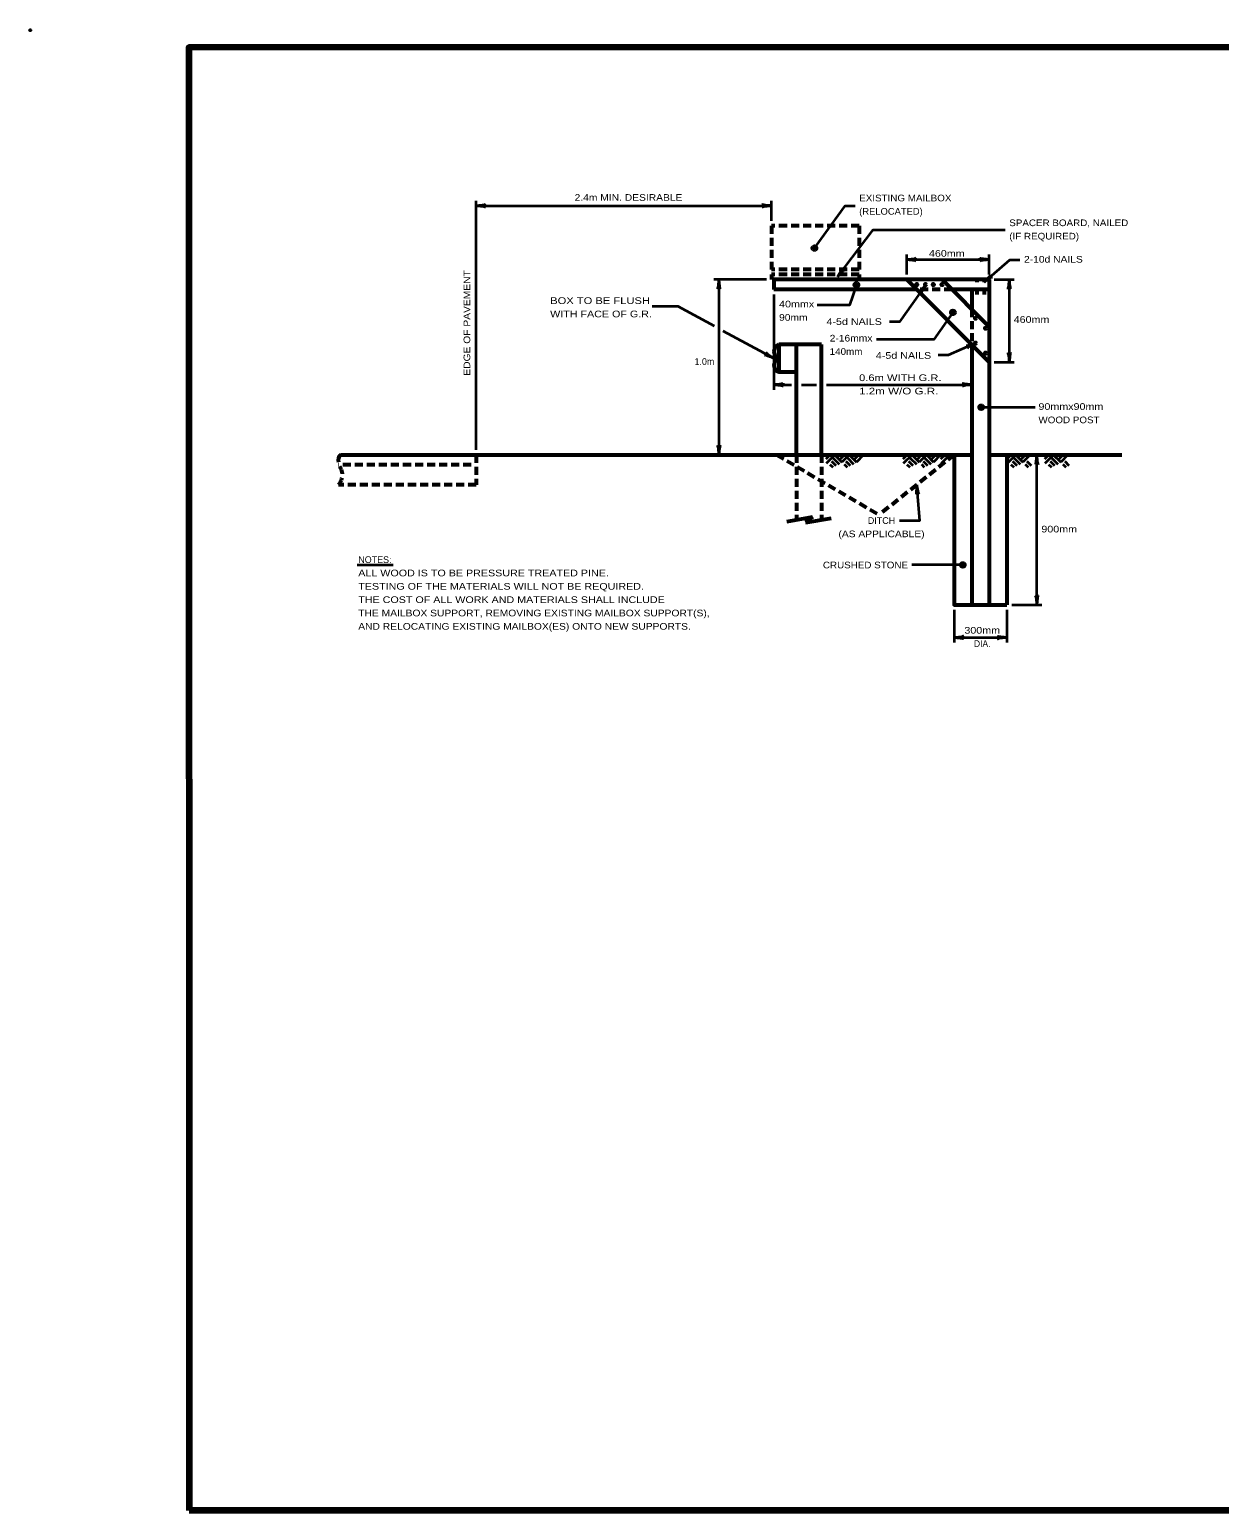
# Model space of a CAD drawing. Extents: x -123 to 733, y -435 to 109.
# Drawn here: x -123 to 305, y -424 to 109 of the extents above; entities that cross this region are included whole.
import ezdxf
from ezdxf.enums import TextEntityAlignment as Align

# ---------------------------------------------------------------- set-up
doc = ezdxf.new("R2010")
doc.units = 0
doc.header["$LTSCALE"] = 0.96
doc.header["$PDMODE"] = 32
doc.header["$PDSIZE"] = 0.48
doc.linetypes.add('MEDIUM_DASHED', pattern=[4.5, 3, -1.5])
doc.layers.add('1', color=7, linetype='Continuous', lineweight=35)

msp = doc.modelspace()

# ---------------------------------------------------------------- hatches: boundary and pattern name
at = {"layer": '1'}
for points in [[(160.1971, 29.9618, 1), (158.3971, 29.9618, 1)], [(175.3246, 16.7553, 1), (173.5246, 16.7553, 1)], [(196.2928, 16.8584, 1), (195.8428, 16.8584, 1)], [(199.4428, 16.8584, 1), (198.9928, 16.8584, 1)], [(202.2706, 16.8584, 1), (201.8206, 16.8584, 1)], [(205.4206, 16.8584, 1), (204.9706, 16.8584, 1)], [(209.9805, 6.8504, 1), (208.1805, 6.8504, 1)], [(217.4428, 4.727, 1), (216.9928, 4.727, 1)], [(221.0428, 1.1271, 1), (220.5928, 1.1271, 1)], [(217.4428, -4.1825, 1), (216.9928, -4.1825, 1)], [(221.0428, -7.7825, 1), (220.5928, -7.7825, 1)], [(220.1572, -27.2664, 1), (218.3572, -27.2664, 1)], [(213.5562, -83.9444, 1), (211.7561, -83.9444, 1)]]:
    msp.add_hatch(color=256, dxfattribs=at).paths.add_polyline_path(points)

# ---------------------------------------------------------------- linework, layer by layer
for p, q in [((37.6678, -42.5417), (37.6678, 47.0084)), ((37.6678, 45.2084), (143.8678, 45.2084)), ((143.8678, 39.8084), (143.8678, 47.0084)), ((192.4678, 20.4584), (192.4678, 27.6584)), ((222.1678, 20.4584), (222.1678, 27.6584)), ((192.4678, 25.8584), (222.1678, 25.8584)), ((142.0678, 18.6584), (123.1678, 18.6584)), ((124.9678, 18.6584), (124.9678, -44.3417)), ((223.9678, 18.6584), (231.1678, 18.6584)), ((229.3678, 18.6584), (229.3678, -11.0416)), ((144.6553, 13.2584), (144.6553, -20.9416)), ((110.26, 8.9859), (100.9414, 8.9859)), ((123.3855, 1.868), (110.26, 8.9859)), ((144.6381, -9.6573), (126.55, 0.152)), ((223.9678, -11.0416), (231.1678, -11.0416)), ((144.6553, -19.1416), (151.0678, -19.1416)), ((154.6678, -19.1416), (160.0678, -19.1416)), ((163.6678, -19.1416), (215.8678, -19.1416)), ((219.2572, -27.2664), (238.7059, -27.2664)), ((164.9885, -44.3897), (163.4045, -45.9737)), ((166.6925, -44.3897), (163.5485, -47.5337)), ((164.8445, -47.7977), (165.8765, -48.8057)), ((165.4445, -46.6937), (166.9805, -48.2297)), ((165.9965, -45.5417), (168.2285, -47.7497)), ((166.5725, -44.3897), (169.2125, -47.0297)), ((168.3965, -44.3897), (167.7245, -45.0857)), ((170.1245, -44.3897), (168.4685, -46.0457)), ((171.8285, -44.3897), (169.2125, -47.0297)), ((170.0285, -47.7257), (171.0605, -48.7577)), ((170.6525, -46.6217), (172.1885, -48.1577)), ((171.2045, -45.4697), (173.4125, -47.6777)), ((171.8285, -44.3897), (174.3965, -46.9577)), ((173.5325, -44.3897), (172.9085, -45.0137)), ((175.2605, -44.3897), (173.6765, -45.9737)), ((176.9645, -44.3897), (174.3965, -46.9577)), ((192.705, -44.3897), (191.121, -45.9737)), ((194.409, -44.3897), (191.265, -47.5337)), ((192.561, -47.7977), (193.593, -48.8057)), ((193.161, -46.6937), (194.697, -48.2297)), ((193.713, -45.5417), (195.945, -47.7497)), ((194.289, -44.3897), (196.929, -47.0297)), ((196.113, -44.3897), (195.441, -45.0857)), ((197.841, -44.3897), (196.185, -46.0457)), ((199.545, -44.3897), (196.929, -47.0297)), ((197.745, -47.7257), (198.777, -48.7577)), ((198.369, -46.6217), (199.905, -48.1577)), ((198.921, -45.4697), (201.129, -47.6777)), ((199.545, -44.3897), (202.113, -46.9577)), ((201.249, -44.3897), (200.625, -45.0137)), ((202.977, -44.3897), (201.393, -45.9737)), ((204.681, -44.3897), (202.113, -46.9577)), ((206.265, -44.3897), (204.681, -45.9737)), ((207.969, -44.3897), (204.825, -47.5337)), ((230.0518, -44.3897), (228.4678, -45.9737)), ((231.7558, -44.3897), (228.6118, -47.5337)), ((229.9078, -47.7977), (230.9398, -48.8057)), ((230.5078, -46.6937), (232.0438, -48.2297)), ((231.0598, -45.5417), (233.2918, -47.7497)), ((231.6358, -44.3897), (234.2758, -47.0297)), ((233.4598, -44.3897), (232.7878, -45.0857)), ((235.1878, -44.3897), (233.5318, -46.0457)), ((236.8918, -44.3897), (234.2758, -47.0297)), ((235.0918, -47.7257), (236.1238, -48.7577)), ((235.7158, -46.6217), (237.2518, -48.1577)), ((239.2678, -98.3417), (239.2678, -44.3417)), ((243.6118, -44.3897), (242.0278, -45.9737)), ((245.3158, -44.3897), (242.1718, -47.5337)), ((243.4678, -47.7977), (244.4998, -48.8057)), ((244.0678, -46.6937), (245.6038, -48.2297)), ((244.6198, -45.5417), (246.8518, -47.7497)), ((245.1958, -44.3897), (247.8358, -47.0297)), ((247.0198, -44.3897), (246.3478, -45.0857)), ((248.7478, -44.3897), (247.0918, -46.0457)), ((250.4518, -44.3897), (247.8358, -47.0297)), ((248.6518, -47.7257), (249.6838, -48.7577)), ((249.2758, -46.6217), (250.8118, -48.1577)), ((-5.1125, -83.9486), (7.8309, -83.9486)), ((212.6562, -83.9444), (194.3694, -83.9444)), ((209.5678, -100.1417), (209.5678, -111.8417)), ((228.4678, -100.1417), (228.4678, -111.8417)), ((230.2678, -98.3417), (241.0678, -98.3417)), ((209.5678, -110.0417), (228.4678, -110.0417))]:
    msp.add_line(p, q, dxfattribs=at)
at = {"layer": '1', "linetype": 'MEDIUM_DASHED', "lineweight": 53}
for p, q in [((175.3678, 38.0084), (175.3678, 22.2584)), ((175.3678, 22.2584), (143.8678, 22.2584)), ((175.3678, 20.4584), (143.8678, 20.4584)), ((143.8678, 20.4584), (143.8678, 18.6584)), ((175.3678, 20.4584), (175.3678, 18.6584)), ((208.7956, 15.0584), (196.0678, 15.0584)), ((215.8678, 7.9863), (215.8678, -4.7416)), ((145.6678, -44.3417), (182.5678, -65.9417)), ((152.8678, -44.3417), (152.8678, -67.6979)), ((161.8678, -44.3417), (161.8678, -67.6979)), ((209.5678, -44.3417), (182.5678, -65.9417)), ((35.8678, -47.9417), (-11.8322, -47.9417))]:
    msp.add_line(p, q, dxfattribs=at)
at = {"layer": '1', "lineweight": 53}
for p, q in [((222.1678, 18.6584), (144.7678, 18.6584)), ((144.7678, 18.6584), (144.7678, 15.0584)), ((192.4678, 18.6584), (222.1678, -11.0416)), ((205.1956, 18.6584), (222.1678, 1.6863)), ((217.6678, 18.6584), (217.6678, 17.7584)), ((220.3678, 18.6584), (220.3678, 17.7584)), ((222.1678, 18.6584), (222.1678, -98.3417)), ((196.0678, 15.0584), (144.7678, 15.0584)), ((222.1678, 15.0584), (208.7956, 15.0584)), ((215.8678, 15.0584), (215.8678, 7.9863)), ((217.6678, 15.0584), (217.6678, 13.2584)), ((220.3678, 15.0584), (220.3678, 13.2584)), ((146.5678, -4.7416), (146.5678, -14.6416)), ((152.8678, -44.3417), (152.8678, -4.7416)), ((161.8678, -44.3417), (161.8678, -4.7416)), ((215.8678, -4.7416), (215.8678, -98.3417)), ((152.8678, -14.6416), (146.5678, -14.6416)), ((-10.9322, -44.3417), (176.731, -44.3417)), ((191.121, -44.3417), (209.5678, -44.3417)), ((209.5678, -44.3417), (215.8678, -44.3417)), ((228.4678, -44.3417), (228.4678, -98.3417)), ((228.4678, -44.3417), (269.8678, -44.3417)), ((149.4296, -68.2988), (158.6699, -66.6835)), ((158.6699, -66.6835), (156.0654, -68.712)), ((156.0654, -68.712), (165.3059, -67.0969))]:
    msp.add_line(p, q, dxfattribs=at)
at = {"layer": '1', "lineweight": 158}
msp.add_line((726.0936, -423.9063), (-65.5064, -423.9063), dxfattribs=at)
msp.add_lwpolyline([(726.0936, 102.1937), (-65.6064, 102.0937), (-65.5064, -423.9063)], dxfattribs=at)
at = {"layer": '1'}
for points in [[(159.2971, 29.9618), (170.3959, 45.2084), (173.9959, 45.2084)], [(167.5618, 19.6206), (180.4489, 36.5898), (227.868, 36.5898)], [(220.3678, 17.7584), (229.5931, 25.7036), (233.1931, 25.7036)], [(174.4246, 16.7553), (171.9388, 9.4016), (160.2606, 9.4016)], [(199.2178, 16.6334), (189.9484, 3.4565), (186.3484, 3.4565)], [(209.0805, 6.8504), (202.1949, -2.8489), (181.5673, -2.8489)], [(217.2178, -4.1824), (207.3454, -8.5128), (203.7454, -8.5128)], [(189.8712, -67.9961), (197.2123, -67.9961), (196.0678, -55.1417)]]:
    msp.add_lwpolyline(points, dxfattribs=at)
at = {"layer": '1', "linetype": 'MEDIUM_DASHED', "lineweight": 53}
for points in [[(175.3678, 38.0084), (143.8678, 38.0084), (143.8678, 22.2584)], [(37.6678, -44.3417), (37.6678, -55.1417), (-11.8322, -55.1417)]]:
    msp.add_lwpolyline(points, dxfattribs=at)
at = {"layer": '1', "lineweight": 53}
for points in [[(161.8678, -4.7416), (152.8678, -4.7416), (146.5678, -4.7416)], [(163.4045, -44.3417), (176.731, -44.3417), (209.5678, -44.3417)], [(209.5678, -44.3417), (209.5678, -98.3417), (228.4678, -98.3417)], [(222.1678, -44.3417), (228.4678, -44.3417), (250.0474, -44.3417)]]:
    msp.add_lwpolyline(points, dxfattribs=at)
at = {"layer": '1'}
for centre in [(159.2971, 29.9618), (174.4246, 16.7553), (209.0805, 6.8504), (219.2572, -27.2664), (212.6561, -83.9444)]:
    msp.add_circle(centre, 0.9, dxfattribs=at)
at = {"layer": '1', "lineweight": 53}
for centre in [(196.0678, 16.8584), (199.2178, 16.8584), (202.0456, 16.8584), (205.1956, 16.8584), (217.2178, 4.727), (220.8178, 1.1271), (217.2178, -4.1825), (220.8178, -7.7825)]:
    msp.add_circle(centre, 0.225, dxfattribs=at)
for centre, radius, start, end in [((147.3694, -7.2167), 2.6016, 107.94525, 252.05475), ((147.3694, -12.1667), 2.6016, 107.94525, 252.05475), ((-9.7703, -46.1971), 2.1892, 122.05444, 201.60153)]:
    msp.add_arc(centre, radius, start, end, dxfattribs=at)
at = {"layer": '1', "linetype": 'MEDIUM_DASHED', "lineweight": 53}
msp.add_arc((-15.5148, -51.5417), 5.1499, 315.64968, 44.35032, dxfattribs=at)
at = {"layer": '1', "lineweight": 40}
for centre, major_axis, ratio, start_param, end_param in [((39.0124, 44.9545), (-2.1077, 0.2108), 0.07063, 3.14071475, 5.41810995), ((39.0124, 44.9545), (-2.1077, 0.2108), 0.07063, 3.14071475, 5.41810995), ((38.9772, 45.54), (-2.1428, -0.1874), 0.122415, 0.89635335, 3.14159265), ((38.9772, 45.54), (-2.1428, -0.1874), 0.122415, 0.89635335, 3.14159265), ((142.5584, 44.8768), (2.1428, 0.1874), 0.122415, 0.89635335, 3.14159265), ((142.5584, 44.8768), (2.1428, 0.1874), 0.122415, 0.89635335, 3.14159265), ((142.5232, 45.4623), (2.1077, -0.2108), 0.07063, 3.14071475, 5.41810995), ((142.5232, 45.4623), (2.1077, -0.2108), 0.07063, 3.14071475, 5.41810995), ((168.0897, 20.8639), (-1.1468, -1.8198), 0.122415, 0.89635335, 3.14159265), ((168.0897, 20.8639), (-1.1468, -1.8198), 0.122415, 0.89635335, 3.14159265), ((168.5772, 20.5378), (-1.4426, -1.5511), 0.07063, 3.14071475, 5.41810995), ((168.5772, 20.5378), (-1.4426, -1.5511), 0.07063, 3.14071475, 5.41810995), ((193.8124, 25.6045), (-2.1077, 0.2108), 0.07063, 3.14071475, 5.41810995), ((193.8124, 25.6045), (-2.1077, 0.2108), 0.07063, 3.14071475, 5.41810995), ((193.7772, 26.19), (-2.1428, -0.1874), 0.122415, 0.89635335, 3.14159265), ((193.7772, 26.19), (-2.1428, -0.1874), 0.122415, 0.89635335, 3.14159265), ((220.8584, 25.5268), (2.1428, 0.1874), 0.122415, 0.89635335, 3.14159265), ((220.8584, 25.5268), (2.1428, 0.1874), 0.122415, 0.89635335, 3.14159265), ((220.8232, 26.1123), (2.1077, -0.2108), 0.07063, 3.14071475, 5.41810995), ((220.8232, 26.1123), (2.1077, -0.2108), 0.07063, 3.14071475, 5.41810995), ((124.7139, 17.3138), (0.2108, 2.1077), 0.07063, 3.14071475, 5.41810995), ((124.7139, 17.3138), (0.2108, 2.1077), 0.07063, 3.14071475, 5.41810995), ((125.2994, 17.349), (-0.1874, 2.1428), 0.122415, 0.89635335, 3.14159265), ((125.2994, 17.349), (-0.1874, 2.1428), 0.122415, 0.89635335, 3.14159265), ((198.2365, 15.6797), (1.3851, 1.6026), 0.07063, 3.14071475, 5.41810995), ((198.2365, 15.6797), (1.3851, 1.6026), 0.07063, 3.14071475, 5.41810995), ((198.7356, 15.3716), (1.0796, 1.8604), 0.122415, 0.89635335, 3.14159265), ((198.7356, 15.3716), (1.0796, 1.8604), 0.122415, 0.89635335, 3.14159265), ((221.1436, 18.8641), (-1.5014, -1.5404), 0.122415, 0.89635335, 3.14159265), ((221.1436, 18.8641), (-1.5014, -1.5404), 0.122415, 0.89635335, 3.14159265), ((221.5523, 18.4435), (-1.7346, -1.2158), 0.07063, 3.14071475, 5.41810995), ((221.5523, 18.4435), (-1.7346, -1.2158), 0.07063, 3.14071475, 5.41810995), ((229.1139, 17.3138), (0.2108, 2.1077), 0.07063, 3.14071475, 5.41810995), ((229.1139, 17.3138), (0.2108, 2.1077), 0.07063, 3.14071475, 5.41810995), ((229.6994, 17.349), (-0.1874, 2.1428), 0.122415, 0.89635335, 3.14159265), ((229.6994, 17.349), (-0.1874, 2.1428), 0.122415, 0.89635335, 3.14159265), ((215.8845, -4.49), (2.0149, 0.6536), 0.07063, 3.14071475, 5.41810995), ((215.8845, -4.49), (2.0149, 0.6536), 0.07063, 3.14071475, 5.41810995), ((216.1518, -5.012), (1.8871, 1.0324), 0.122415, 0.89635335, 3.14159265), ((216.1518, -5.012), (1.8871, 1.0324), 0.122415, 0.89635335, 3.14159265), ((143.329, -9.3245), (1.973, -0.8568), 0.122415, 0.89635335, 3.14159265), ((143.329, -9.3245), (1.973, -0.8568), 0.122415, 0.89635335, 3.14159265), ((143.5772, -8.7931), (1.7523, -1.1901), 0.07063, 3.14071475, 5.41810995), ((143.5772, -8.7931), (1.7523, -1.1901), 0.07063, 3.14071475, 5.41810995), ((229.0362, -9.7322), (0.1874, -2.1428), 0.122415, 0.89635335, 3.14159265), ((229.0362, -9.7322), (0.1874, -2.1428), 0.122415, 0.89635335, 3.14159265), ((229.6217, -9.697), (-0.2108, -2.1077), 0.07063, 3.14071475, 5.41810995), ((229.6217, -9.697), (-0.2108, -2.1077), 0.07063, 3.14071475, 5.41810995), ((145.9999, -19.3955), (-2.1077, 0.2108), 0.07063, 3.14071475, 5.41810995), ((145.9647, -18.81), (-2.1428, -0.1874), 0.122415, 0.89635335, 3.14159265), ((214.5584, -19.4732), (2.1428, 0.1874), 0.122415, 0.89635335, 3.14159265), ((214.5584, -19.4732), (2.1428, 0.1874), 0.122415, 0.89635335, 3.14159265), ((214.5232, -18.8877), (2.1077, -0.2108), 0.07063, 3.14071475, 5.41810995), ((214.5232, -18.8877), (2.1077, -0.2108), 0.07063, 3.14071475, 5.41810995), ((124.6362, -43.0323), (0.1874, -2.1428), 0.122415, 0.89635335, 3.14159265), ((124.6362, -43.0323), (0.1874, -2.1428), 0.122415, 0.89635335, 3.14159265), ((125.2217, -42.9971), (-0.2108, -2.1077), 0.07063, 3.14071475, 5.41810995), ((125.2217, -42.9971), (-0.2108, -2.1077), 0.07063, 3.14071475, 5.41810995), ((239.0139, -45.6863), (0.2108, 2.1077), 0.07063, 3.14071475, 5.41810995), ((239.0139, -45.6863), (0.2108, 2.1077), 0.07063, 3.14071475, 5.41810995), ((239.5994, -45.6511), (-0.1874, 2.1428), 0.122415, 0.89635335, 3.14159265), ((239.5994, -45.6511), (-0.1874, 2.1428), 0.122415, 0.89635335, 3.14159265), ((195.9341, -56.5035), (0.023, 2.1181), 0.07063, 3.14071475, 5.41810995), ((196.5142, -56.4166), (-0.3767, 2.1178), 0.122415, 0.89635335, 3.14159265), ((238.9362, -97.0323), (0.1874, -2.1428), 0.122415, 0.89635335, 3.14159265), ((238.9362, -97.0323), (0.1874, -2.1428), 0.122415, 0.89635335, 3.14159265), ((239.5217, -96.9971), (-0.2108, -2.1077), 0.07063, 3.14071475, 5.41810995), ((239.5217, -96.9971), (-0.2108, -2.1077), 0.07063, 3.14071475, 5.41810995), ((210.9124, -110.2956), (-2.1077, 0.2108), 0.07063, 3.14071475, 5.41810995), ((210.8772, -109.7101), (-2.1428, -0.1874), 0.122415, 0.89635335, 3.14159265), ((227.1584, -110.3733), (2.1428, 0.1874), 0.122415, 0.89635335, 3.14159265), ((227.1584, -110.3733), (2.1428, 0.1874), 0.122415, 0.89635335, 3.14159265), ((227.1232, -109.7878), (2.1077, -0.2108), 0.07063, 3.14071475, 5.41810995), ((227.1232, -109.7878), (2.1077, -0.2108), 0.07063, 3.14071475, 5.41810995)]:
    msp.add_ellipse(centre, major_axis=major_axis, ratio=ratio, start_param=start_param, end_param=end_param, dxfattribs=at)
at = {"layer": '1'}
msp.add_point((-122.6064, 108.2937), dxfattribs=at)

# ---------------------------------------------------------------- texts
for s, width, p in [('2.4m MIN. DESIRABLE', 1.15, (73.0794, 46.9724)), ('EXISTING MAILBOX', 1.1, (175.4062, 46.7814)), ('(RELOCATED)', 1.05, (175.4062, 41.9814)), ('SPACER BOARD, NAILED', 1.1, (229.358, 37.8677)), ('(IF REQUIRED)', 1.1, (229.358, 33.0677)), ('460mm', 1.2, (200.478, 26.8677)), ('2-10d NAILS', 1.15, (234.6584, 24.7476)), ('BOX TO BE FLUSH', 1.25, (64.2983, 9.8878)), ('40mmx', 1.2, (146.596, 8.6503)), ('WITH FACE OF G.R.', 1.2, (64.2983, 5.0878)), ('90mm', 1.15, (146.596, 3.8503)), ('460mm', 1.2, (230.9338, 3.0993)), ('4-5d NAILS', 1.2, (163.6344, 2.3476)), ('2-16mmx', 1.15, (164.7892, -3.615)), ('140mm', 1.1, (164.7892, -8.415)), ('4-5d NAILS', 1.2, (181.3742, -9.8391)), ('0.6m WITH G.R.', 1.25, (175.3576, -17.8427)), ('1.2m W/O G.R.', 1.3, (175.3576, -22.6427)), ('90mmx90mm', 1.2, (239.8444, -28.1946)), ('WOOD POST', 1.1, (239.8444, -32.9946)), ('900mm', 1.2, (240.888, -72.2685)), ('CRUSHED STONE', 1.1, (162.3542, -85.1869)), ('ALL WOOD IS TO BE PRESSURE TREATED PINE.', 1.2, (-4.6914, -88.047)), ('TESTING OF THE MATERIALS WILL NOT BE REQUIRED.', 1.2, (-4.6914, -92.847)), ('THE COST OF ALL WORK AND MATERIALS SHALL INCLUDE', 1.2, (-4.6914, -97.647)), ('THE MAILBOX SUPPORT, REMOVING EXISTING MAILBOX SUPPORT(S),', 1.15, (-4.6914, -102.447)), ('AND RELOCATING EXISTING MAILBOX(ES) ONTO NEW SUPPORTS.', 1.15, (-4.6914, -107.247))]:
    msp.add_text(s, height=2.4, dxfattribs=dict(at, width=width)).set_placement(p)
at = {"layer": '1', "width": 1.15}
msp.add_text('EDGE OF PAVEMENT', height=2.4, rotation=90, dxfattribs=at).set_placement((35.5621, -15.904))
at = {"layer": '1'}
for s, p in [('1.0m', (116.1879, -12.0249)), ('NOTES:', (-4.6914, -83.247))]:
    msp.add_text(s, height=2.4, dxfattribs=at).set_placement(p)
msp.add_text('DITCH', height=2.4, dxfattribs=at).set_placement((183.4255, -69.1873), align=Align.CENTER)
for s, width, p in [('(AS APPLICABLE)', 1.15, (183.4256, -73.9873)), ('300mm', 1.2, (219.6325, -108.6489)), ('DIA.', 0.95, (219.6324, -113.4489))]:
    msp.add_text(s, height=2.4, dxfattribs=dict(at, width=width)).set_placement(p, align=Align.CENTER)

doc.saveas('drawing.dxf')
